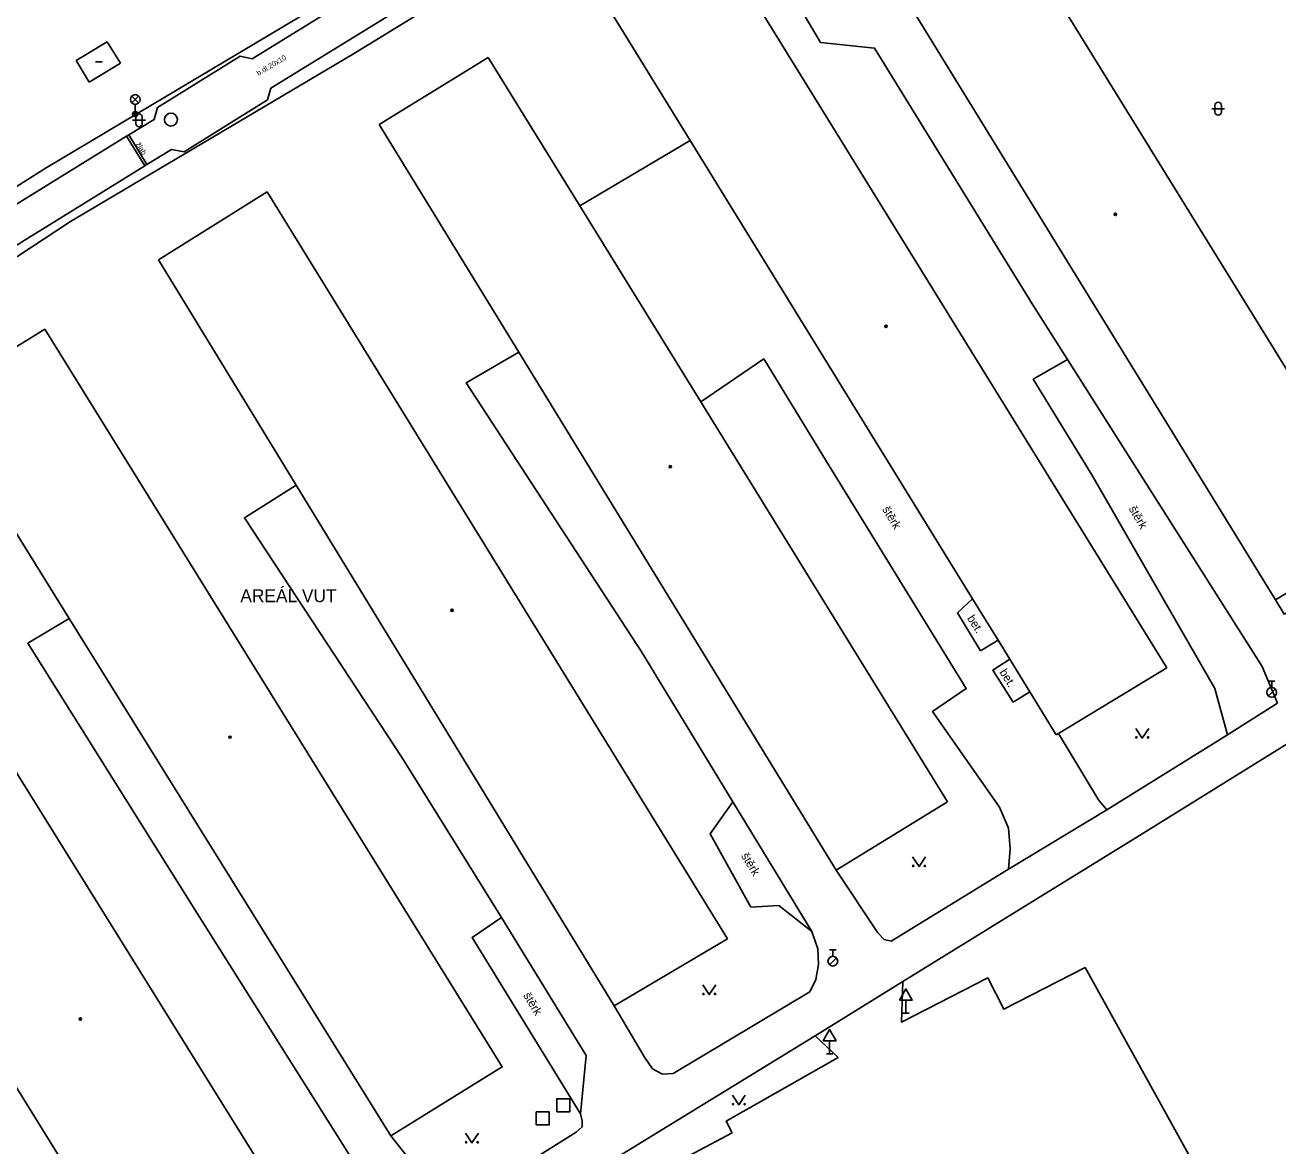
# Model space of a CAD drawing. Extents: x -600391 to -599491, y -1160176 to -1159402.
# Drawn here: x -599671 to -599574.3, y -1159533.6 to -1159447 of the extents above; entities that cross this region are included whole.
import ezdxf

# ---------------------------------------------------------------- set-up
doc = ezdxf.new("R2010")
doc.units = 0
for name, color, linetype in [('Level 10', 7, 'Continuous'), ('Level 11', 7, 'Continuous'), ('Level 24', 7, 'Continuous'), ('Level 26', 7, 'Continuous'), ('Level 27', 7, 'Continuous'), ('Level 28', 7, 'Continuous'), ('Level 33', 7, 'Continuous'), ('Level 34', 7, 'Continuous'), ('Level 36', 7, 'Continuous'), ('Level 39', 7, 'Continuous'), ('Level 40', 7, 'Continuous'), ('Level 42', 7, 'Continuous'), ('Level 5', 7, 'Continuous'), ('Level 7', 7, 'Continuous')]:
    doc.layers.add(name, color=color, linetype=linetype)

msp = doc.modelspace()

# ---------------------------------------------------------------- linework, layer by layer
at = {"layer": 'Level 10'}
for points in [[(-599640.08, -1159444.49), (-599640.17, -1159444.54), (-599652.06, -1159451.89)], [(-599646.86, -1159445.52), (-599653.49, -1159449.62)], [(-599654.43, -1159449.41), (-599660.81, -1159453.37)], [(-599654.43, -1159449.41), (-599653.49, -1159449.62)], [(-599652.06, -1159451.89), (-599652.32, -1159452.8)], [(-599660.81, -1159453.37), (-599661.07, -1159454.32)], [(-599652.32, -1159452.8), (-599658.76, -1159456.8)], [(-599661.07, -1159454.32), (-599663.03, -1159455.5), (-599663.11, -1159455.55)], [(-599663.11, -1159455.55), (-599663.2, -1159455.6), (-599674.97, -1159462.86)], [(-599659.72, -1159456.62), (-599661.63, -1159457.79), (-599661.71, -1159457.84)], [(-599659.72, -1159456.62), (-599658.76, -1159456.8)], [(-599661.71, -1159457.84), (-599661.8, -1159457.89), (-599673.5, -1159465.12)], [(-599593.25, -1159468.56), (-599590.52, -1159472.86), (-599575.49, -1159496.57), (-599574.31, -1159499.4)], [(-599574.46, -1159491.42), (-599573.8, -1159492.53), (-599572.93, -1159492.13), (-599572, -1159493.88), (-599572.89, -1159494.42), (-599571.21, -1159496.87), (-599570.52, -1159497.11)], [(-599623.45, -1159495.4), (-599616.37, -1159507.04), (-599610.28, -1159517.05), (-599609.8, -1159518.4), (-599609.75, -1159519.6), (-599609.96, -1159520.77), (-599610.42, -1159521.72)], [(-599584.95, -1159509.64), (-599571.73, -1159501.42), (-599568.06, -1159499.49)], [(-599574.31, -1159499.4), (-599578.16, -1159501.87)], [(-599578.16, -1159501.87), (-599587.48, -1159507.65)], [(-599634.23, -1159515.98), (-599641.9, -1159503.64)], [(-599587.48, -1159507.65), (-599595.09, -1159512.23)], [(-599603.25, -1159520.91), (-599584.95, -1159509.64)], [(-599604.15, -1159517.8), (-599604.69, -1159517.68), (-599605.17, -1159517.16), (-599608.38, -1159512.31)], [(-599595.09, -1159512.23), (-599604.15, -1159517.8)], [(-599657.59, -1159515.91), (-599644.12, -1159537.28), (-599643.32, -1159539.19), (-599643.15, -1159540.71), (-599643.15, -1159541.59)], [(-599634.23, -1159515.98), (-599627.7, -1159526.63), (-599628.14, -1159531.14)], [(-599589.16, -1159519.85), (-599595.44, -1159523.06), (-599596.67, -1159520.65)], [(-599589.16, -1159519.85), (-599574.5, -1159546.33)], [(-599596.67, -1159520.65), (-599603.35, -1159524.06), (-599603.25, -1159520.91)], [(-599610.42, -1159521.72), (-599620.97, -1159528.04)], [(-599620.97, -1159528.04), (-599621.8, -1159528.08), (-599622.57, -1159527.66), (-599623.19, -1159526.76), (-599625.54, -1159522.8)], [(-599644.9, -1159546.55), (-599627.66, -1159535.93), (-599610.01, -1159525.11)], [(-599616.42, -1159532.62), (-599616.9, -1159531.72), (-599608.24, -1159526.79), (-599610.01, -1159525.11)], [(-599628.02, -1159532.14), (-599628, -1159531.68), (-599628.14, -1159531.14)], [(-599642.78, -1159532.85), (-599640.64, -1159535.56), (-599639.46, -1159537.33), (-599636.91, -1159537.86)], [(-599628.02, -1159532.14), (-599628.47, -1159532.56), (-599636.91, -1159537.86)], [(-599616.42, -1159532.62), (-599625.16, -1159537.25)]]:
    msp.add_lwpolyline(points, dxfattribs=at)
at = {"layer": 'Level 11'}
for points in [[(-599609.18, -1159434.92), (-599615.21, -1159438.84), (-599609.6, -1159448.36), (-599605.42, -1159448.79), (-599593.25, -1159468.56)], [(-599628.19, -1159460.98), (-599619.67, -1159455.93)], [(-599623.45, -1159495.4), (-599636.96, -1159474.66), (-599632.9, -1159472.29)], [(-599609.15, -1159480.73), (-599613.99, -1159472.81), (-599618.84, -1159476.14)], [(-599588.65, -1159481.77), (-599593.17, -1159474.38), (-599590.52, -1159472.86)], [(-599609.15, -1159480.73), (-599598.35, -1159498.29), (-599600.94, -1159500.06), (-599595.78, -1159507.45), (-599595.08, -1159509.08), (-599594.95, -1159510.66), (-599595.09, -1159512.23)], [(-599641.9, -1159503.64), (-599654.1, -1159485.09), (-599650.11, -1159482.56)], [(-599588.65, -1159481.77), (-599579.15, -1159498.28), (-599578.16, -1159501.87)], [(-599597.25, -1159495.37), (-599599.03, -1159492.43), (-599597.86, -1159491.35)], [(-599657.59, -1159515.91), (-599670.82, -1159494.77), (-599667.62, -1159492.86)], [(-599595.89, -1159494.55), (-599597.25, -1159495.37)], [(-599594.72, -1159499.34), (-599596.29, -1159496.85), (-599594.99, -1159496.01)], [(-599593.44, -1159498.53), (-599594.72, -1159499.34)], [(-599587.48, -1159507.65), (-599588.13, -1159506.88), (-599591.22, -1159501.76)], [(-599616.37, -1159507.04), (-599618.13, -1159509.51), (-599614.97, -1159515.17), (-599612.83, -1159515.05), (-599610.28, -1159517.05)], [(-599628.14, -1159531.14), (-599636.51, -1159517.52), (-599634.23, -1159515.98)], [(-599603.25, -1159520.91), (-599610.01, -1159525.11)]]:
    msp.add_lwpolyline(points, dxfattribs=at)
at = {"layer": 'Level 24'}
for points in [[(-599663.2, -1159455.6), (-599661.8, -1159457.89)], [(-599663.03, -1159455.5), (-599661.63, -1159457.79)]]:
    msp.add_lwpolyline(points, dxfattribs=at)
at = {"layer": 'Level 26'}
for points in [[(-599629.97, -1159530.98), (-599628.97, -1159530.98), (-599628.97, -1159529.98), (-599629.97, -1159529.98)], [(-599631.55, -1159532), (-599630.55, -1159532), (-599630.55, -1159531), (-599631.55, -1159531)]]:
    msp.add_lwpolyline(points, close=True, dxfattribs=at)
at = {"layer": 'Level 27'}
msp.add_circle((-599659.77, -1159454.32), 0.5, dxfattribs=at)
at = {"layer": 'Level 28'}
for p, q in [((-599575, -1159497.705), (-599574.5, -1159497.705)), ((-599574.75, -1159498.205), (-599574.75, -1159497.705)), ((-599575.008, -1159498.852), (-599574.478, -1159498.322)), ((-599608.908, -1159519.622), (-599608.378, -1159519.092)), ((-599608.9, -1159518.475), (-599608.4, -1159518.475)), ((-599608.65, -1159518.975), (-599608.65, -1159518.475))]:
    msp.add_line(p, q, dxfattribs=at)
for centre in [(-599574.75, -1159498.58), (-599608.65, -1159519.35)]:
    msp.add_circle(centre, 0.375, dxfattribs=at)
at = {"layer": 'Level 33'}
for p, q in [((-599662.795, -1159453.03), (-599662.265, -1159452.5)), ((-599662.795, -1159452.5), (-599662.265, -1159453.03)), ((-599662.53, -1159453.14), (-599662.53, -1159453.89))]:
    msp.add_line(p, q, dxfattribs=at)
for centre, radius in [((-599662.53, -1159452.765), 0.375), ((-599662.53, -1159453.89), 0.2), ((-599662.53, -1159453.89), 0.145), ((-599662.53, -1159453.89), 0.0876)]:
    msp.add_circle(centre, radius, dxfattribs=at)
at = {"layer": 'Level 34'}
for p, q in [((-599603.01, -1159522.362), (-599603.01, -1159523.38)), ((-599603.26, -1159523.38), (-599602.76, -1159523.38)), ((-599608.9, -1159525.502), (-599608.9, -1159526.52)), ((-599609.15, -1159526.52), (-599608.65, -1159526.52))]:
    msp.add_line(p, q, dxfattribs=at)
for points in [[(-599603.51, -1159522.362), (-599602.51, -1159522.362), (-599603.01, -1159521.496)], [(-599609.4, -1159525.502), (-599608.4, -1159525.502), (-599608.9, -1159524.636)]]:
    msp.add_lwpolyline(points, close=True, dxfattribs=at)
at = {"layer": 'Level 36'}
for p, q in [((-599579.386, -1159453.476), (-599578.386, -1159453.476)), ((-599579.136, -1159453.226), (-599579.136, -1159453.726)), ((-599578.636, -1159453.226), (-599578.636, -1159453.726)), ((-599662.736, -1159454.366), (-599661.736, -1159454.366)), ((-599662.486, -1159454.116), (-599662.486, -1159454.616)), ((-599661.986, -1159454.116), (-599661.986, -1159454.616))]:
    msp.add_line(p, q, dxfattribs=at)
for points in [[(-599585.25, -1159501.36), (-599584.75, -1159502.11), (-599584.25, -1159501.36)], [(-599602.49, -1159511.29), (-599601.99, -1159512.04), (-599601.49, -1159511.29)], [(-599618.69, -1159521.18), (-599618.19, -1159521.93), (-599617.69, -1159521.18)], [(-599616.41, -1159529.7), (-599615.91, -1159530.45), (-599615.41, -1159529.7)], [(-599637.02, -1159532.64), (-599636.52, -1159533.39), (-599636.02, -1159532.64)]]:
    msp.add_lwpolyline(points, dxfattribs=at)
for centre in [(-599585.2, -1159502.06), (-599584.301, -1159502.06), (-599602.44, -1159511.99), (-599601.541, -1159511.99), (-599618.64, -1159521.88), (-599617.741, -1159521.88), (-599616.36, -1159530.4), (-599615.461, -1159530.4), (-599636.97, -1159533.34), (-599636.071, -1159533.34)]:
    msp.add_circle(centre, 0.05, dxfattribs=at)
for centre, start, end in [((-599578.886, -1159453.226), 0, 180), ((-599662.236, -1159454.116), 0, 180), ((-599578.886, -1159453.726), 180, 0), ((-599662.236, -1159454.616), 180, 0)]:
    msp.add_arc(centre, 0.25, start, end, dxfattribs=at)
at = {"layer": 'Level 39'}
msp.add_line((-599665.59, -1159449.86), (-599665.09, -1159449.86), dxfattribs=at)
for centre, radius in [((-599586.82, -1159461.65), 0.09), ((-599586.82, -1159461.65), 0.0398), ((-599604.54, -1159470.3), 0.09), ((-599604.54, -1159470.3), 0.0398), ((-599621.21, -1159481.14), 0.09), ((-599621.21, -1159481.14), 0.0398), ((-599638.06, -1159492.23), 0.09), ((-599638.06, -1159492.23), 0.0398), ((-599655.2, -1159502.04), 0.09), ((-599655.2, -1159502.04), 0.0398), ((-599666.76, -1159523.83), 0.09), ((-599666.76, -1159523.83), 0.0398)]:
    msp.add_circle(centre, radius, dxfattribs=at)
at = {"layer": 'Level 5'}
for points in [[(-599601.25, -1159428.82), (-599565.83, -1159486.21)], [(-599609.73, -1159434.02), (-599609.18, -1159434.92), (-599574.46, -1159491.42)], [(-599618.3, -1159439.24), (-599582.84, -1159496.67)], [(-599591.39, -1159501.86), (-599593.44, -1159498.53), (-599594.99, -1159496.01), (-599595.89, -1159494.55), (-599597.86, -1159491.35), (-599619.67, -1159455.93), (-599626.76, -1159444.41)], [(-599667.1, -1159449.74), (-599664.69, -1159448.3)], [(-599664.69, -1159448.3), (-599663.67, -1159449.96)], [(-599643.68, -1159454.69), (-599635.26, -1159449.51)], [(-599635.26, -1159449.51), (-599628.19, -1159460.98), (-599618.84, -1159476.14), (-599599.8, -1159507.04)], [(-599666.08, -1159451.42), (-599667.1, -1159449.74)], [(-599663.67, -1159449.96), (-599666.08, -1159451.42)], [(-599608.38, -1159512.31), (-599632.9, -1159472.29), (-599643.68, -1159454.69)], [(-599660.74, -1159465.16), (-599652.35, -1159459.91)], [(-599652.35, -1159459.91), (-599616.78, -1159517.63)], [(-599625.54, -1159522.8), (-599650.11, -1159482.56), (-599660.74, -1159465.16)], [(-599642.78, -1159532.85), (-599667.62, -1159492.86), (-599678.18, -1159475.86), (-599669.51, -1159470.51)], [(-599669.51, -1159470.51), (-599634.18, -1159527.52), (-599642.78, -1159532.85)], [(-599686.69, -1159480.76), (-599673.4, -1159502.1), (-599650.71, -1159538.53)], [(-599574.46, -1159491.42), (-599565.83, -1159486.21)], [(-599661.66, -1159545.33), (-599684.23, -1159508.9), (-599697.68, -1159487.61)], [(-599591.39, -1159501.86), (-599591.22, -1159501.76), (-599582.84, -1159496.67)], [(-599608.38, -1159512.31), (-599599.8, -1159507.04)], [(-599625.54, -1159522.8), (-599616.78, -1159517.63)]]:
    msp.add_lwpolyline(points, dxfattribs=at)
at = {"layer": 'Level 7'}
for points in [[(-599630.18, -1159439.71), (-599645.66, -1159449.23), (-599667.53, -1159462.19)], [(-599646.2, -1159444.2), (-599646.23, -1159444.22), (-599669.4, -1159458.05), (-599689.55, -1159470.76), (-599714.78, -1159486.36)], [(-599715.95, -1159580.53), (-599718.21, -1159578.15), (-599735.29, -1159547.34), (-599749.06, -1159522.25), (-599750.23, -1159519.23), (-599750.33, -1159516.08), (-599748.44, -1159513.49), (-599743.31, -1159510.14), (-599732.66, -1159503.4), (-599713.52, -1159491.46), (-599689.03, -1159476.34), (-599667.53, -1159462.19)]]:
    msp.add_lwpolyline(points, dxfattribs=at)

# ---------------------------------------------------------------- texts
at = {"layer": 'Level 40'}
for s, height, rotation, p in [('b.dl.20x10', 0.4, 30.69731, (-599653.01, -1159450.94)), ('štěrk', 0.65, 301.19248, (-599604.86, -1159484.43)), ('štěrk', 0.65, 299.9165, (-599585.81, -1159484.39)), ('bet.', 0.65, 302.23234, (-599598.3, -1159492.85)), ('bet.', 0.65, 302.23234, (-599595.81, -1159497.02)), ('štěrk', 0.65, 301.31774, (-599615.76, -1159511.21)), ('štěrk', 0.65, 301.51436, (-599632.59, -1159522))]:
    msp.add_text(s, height=height, rotation=rotation, dxfattribs=at).set_placement(p)
at = {"layer": 'Level 42'}
msp.add_text('žlab', height=0.4, rotation=301.51902, dxfattribs=at).set_placement((-599662.49, -1159456.22))
msp.add_text('AREÁL VUT', height=1, dxfattribs=at).set_placement((-599654.41, -1159491.61))

doc.saveas('drawing.dxf')
